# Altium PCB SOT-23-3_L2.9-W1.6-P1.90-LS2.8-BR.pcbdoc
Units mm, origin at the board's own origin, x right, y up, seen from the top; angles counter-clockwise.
Board outline 16.24 x 15.77 mm, 2 copper layers (Top Layer, Bottom Layer), stack 0.07 mm thick; 1 components, 0 nets, 3 pads, 0 vias.
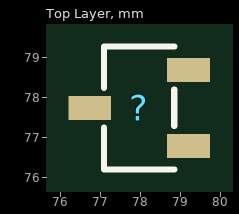
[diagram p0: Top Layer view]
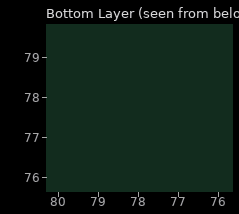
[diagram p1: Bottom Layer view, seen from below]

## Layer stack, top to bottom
Top Solder Mask Layer: solder mask 0.01, Dk 3.3
Top Layer: signal copper 0.035
Bottom Layer: signal copper 0.035
Bottom Solder Mask Layer: solder mask 0.01, Dk 3.3

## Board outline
86.09,69.85 69.85,69.85 69.85,85.622 86.09,85.622

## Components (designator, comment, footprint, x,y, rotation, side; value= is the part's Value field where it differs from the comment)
? "SOT-23-3_L2.9-W1.6-P1.90-LS2.8-BR" SOT-23-3_L2.9-W1.6-P1.90-LS2.8-BR 77.97,77.736 r0 top

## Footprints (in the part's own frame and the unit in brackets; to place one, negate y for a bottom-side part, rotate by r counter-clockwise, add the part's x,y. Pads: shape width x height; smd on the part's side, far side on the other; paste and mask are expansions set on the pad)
SOT-23-3_L2.9-W1.6-P1.90-LS2.8-BR [mm]
  rect 1.07x0.6 smd paste+0 mask+0.051: 1(1.235,-0.95) 2(1.235,0.95) 3(-1.235,0)
  silkscreen extent -0.88,-1.54 0.88,1.54

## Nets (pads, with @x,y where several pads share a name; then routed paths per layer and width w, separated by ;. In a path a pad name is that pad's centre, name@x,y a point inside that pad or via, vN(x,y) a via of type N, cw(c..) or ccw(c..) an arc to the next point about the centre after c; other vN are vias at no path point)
pads on no net: ?.1 ?.2 ?.3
